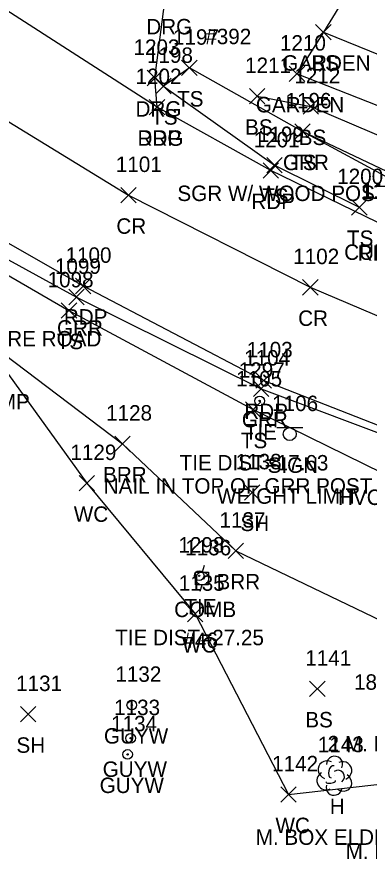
# Model space of a CAD drawing. Extents: x 1761340 to 1763889, y 696770 to 706023.
# Drawn here: x 1761519.1 to 1761564.7, y 700804.8 to 700913.9 of the extents above; entities that cross this region are included whole.
import ezdxf

# ---------------------------------------------------------------- set-up
doc = ezdxf.new("R2010")
doc.units = 0
for name, color, linetype in [('C_A', 7, 'Continuous'), ('C_C', 7, 'Continuous'), ('C_I', 7, 'Continuous'), ('CBP', 7, 'Continuous'), ('D_C', 7, 'Continuous'), ('L_A', 7, 'Continuous'), ('L_C', 7, 'Continuous'), ('L_I', 7, 'Continuous'), ('L_TIC', 7, 'Continuous'), ('LABL', 7, 'Continuous'), ('LAPB', 7, 'Continuous'), ('LAWE', 7, 'Continuous'), ('LELB', 7, 'Continuous'), ('LTD', 7, 'Continuous'), ('P_A', 7, 'Continuous'), ('P_I', 7, 'Continuous'), ('P_TIC', 7, 'Continuous'), ('PET', 7, 'Continuous'), ('PRC', 7, 'Continuous'), ('R_A', 7, 'Continuous'), ('R_C', 7, 'Continuous'), ('R_I', 7, 'Continuous'), ('R_TIC', 7, 'Continuous'), ('RDG', 7, 'Continuous'), ('RGR', 7, 'Continuous'), ('S_A', 7, 'Continuous'), ('S_C', 7, 'Continuous'), ('S_I', 7, 'Continuous'), ('SSGN', 7, 'Continuous'), ('U_A', 7, 'Continuous'), ('U_C', 7, 'Continuous'), ('U_I', 7, 'Continuous'), ('UP', 7, 'Continuous'), ('UPGW', 7, 'Continuous')]:
    doc.layers.add(name, color=color, linetype=linetype)

msp = doc.modelspace()

# ---------------------------------------------------------------- linework, layer by layer
at = {"layer": 'CBP'}
for centre, radius in [((1761550.48, 700864.17), 0.625), ((1761550.48, 700864.17), 0.0833), ((1761542.66, 700841.54), 0.625), ((1761542.66, 700841.54), 0.0833)]:
    msp.add_circle(centre, radius, dxfattribs=at)
at = {"layer": 'L_TIC'}
for points in [[(1761557.73, 700910.94), (1761559.73, 700912.94)], [(1761559.73, 700910.94), (1761557.73, 700912.94)], [(1761557.73, 700910.94), (1761559.73, 700912.94)], [(1761559.73, 700910.94), (1761557.73, 700912.94)], [(1761557.73, 700910.94), (1761559.73, 700912.94)], [(1761559.73, 700910.94), (1761557.73, 700912.94)], [(1761540.39, 700906.3), (1761542.39, 700908.3)], [(1761542.39, 700906.3), (1761540.39, 700908.3)], [(1761554.32, 700905.54), (1761556.32, 700907.54)], [(1761556.32, 700905.54), (1761554.32, 700907.54)], [(1761537.03, 700903.95), (1761539.03, 700905.95)], [(1761539.03, 700903.95), (1761537.03, 700905.95)], [(1761549.16, 700902.64), (1761551.16, 700904.64)], [(1761551.16, 700902.64), (1761549.16, 700904.64)], [(1761556.1, 700901.31), (1761558.1, 700903.31)], [(1761558.1, 700901.31), (1761556.1, 700903.31)], [(1761555.02, 700898.06), (1761557.02, 700900.06)], [(1761557.02, 700898.06), (1761555.02, 700900.06)], [(1761551.4, 700893.7), (1761553.4, 700895.7)], [(1761553.4, 700893.7), (1761551.4, 700895.7)], [(1761562.38, 700888.25), (1761564.38, 700890.25)], [(1761564.38, 700888.25), (1761562.38, 700890.25)], [(1761524.81, 700874.88), (1761526.81, 700876.88)], [(1761526.81, 700874.88), (1761524.81, 700876.88)], [(1761548.64, 700862.05), (1761550.64, 700864.05)], [(1761550.64, 700862.05), (1761548.64, 700864.05)], [(1761531.73, 700857.63), (1761533.73, 700859.63)], [(1761533.73, 700857.63), (1761531.73, 700859.63)], [(1761527.13, 700852.52), (1761529.13, 700854.52)], [(1761529.13, 700852.52), (1761527.13, 700854.52)], [(1761548.51, 700851.32), (1761550.51, 700853.32)], [(1761550.51, 700851.32), (1761548.51, 700853.32)], [(1761546.41, 700843.77), (1761548.41, 700845.77)], [(1761548.41, 700843.77), (1761546.41, 700845.77)], [(1761541.13, 700835.59), (1761543.13, 700837.59)], [(1761543.13, 700835.59), (1761541.13, 700837.59)], [(1761556.95, 700825.9), (1761558.95, 700827.9)], [(1761558.95, 700825.9), (1761556.95, 700827.9)], [(1761519.52, 700822.61), (1761521.52, 700824.61)], [(1761521.52, 700822.61), (1761519.52, 700824.61)], [(1761553.23, 700812.21), (1761555.23, 700814.21)], [(1761555.23, 700812.21), (1761553.23, 700814.21)]]:
    msp.add_lwpolyline(points, dxfattribs=at)
at = {"layer": 'LABL'}
msp.add_lwpolyline([(1761502.66, 700832.33), (1761503.71, 700859.79), (1761494.96, 700875.25), (1761503.4, 700881.5), (1761510.45, 700875.51), (1761532.73, 700858.63), (1761547.41, 700844.77), (1761568.49, 700834.64), (1761575.59, 700833.99)], dxfattribs=at)
at = {"layer": 'LAPB'}
for points in [[(1761558.73, 700911.94), (1761555.32, 700906.54), (1761591.97, 700892.11), (1761594.9, 700897.25)], [(1761558.73, 700911.94), (1761594.9, 700897.25)]]:
    msp.add_lwpolyline(points, dxfattribs=at)
at = {"layer": 'LAWE'}
msp.add_lwpolyline([(1761514.71, 700872.07), (1761528.13, 700853.52), (1761542.13, 700836.59), (1761554.23, 700813.21), (1761575.51, 700815.64)], dxfattribs=at)
at = {"layer": 'LELB'}
for points in [[(1761570.3, 700930.84), (1761558.73, 700911.94)], [(1761602.62, 700879.96), (1761585.98, 700886.58), (1761568.65, 700893.05), (1761556.02, 700899.06), (1761541.39, 700907.3), (1761538.03, 700904.95), (1761552.4, 700894.7), (1761563.38, 700889.25)], [(1761550.16, 700903.64), (1761557.1, 700902.31), (1761589.88, 700888.3), (1761604.26, 700883.61)], [(1761502.66, 700832.33), (1761493.7, 700859.4), (1761488.55, 700870.2), (1761483.14, 700875.04), (1761493.67, 700887.92), (1761503.53, 700888.77), (1761525.81, 700875.88), (1761549.64, 700863.05), (1761575.92, 700850.18), (1761596.96, 700845.7)]]:
    msp.add_lwpolyline(points, dxfattribs=at)
at = {"layer": 'LTD'}
msp.add_line((1761560.13, 700815.69), (1761560.13, 700815.69), dxfattribs=at)
msp.add_line((1761560.13, 700815.69), (1761560.13, 700815.69), dxfattribs=at)
msp.add_arc((1761560.18, 700817.12), 1.05, 335.5272, 180.9563, dxfattribs=at)
for centre, major_axis, ratio, start_param, end_param in [((1761559.34, 700816.36), (1.21, -0.51), 0.895232, 1.570796, 4.712389), ((1761561.18, 700816.27), (-1.14, -0.48), 0.949671, 1.570796, 4.712389), ((1761559.93, 700816.15), (-0.208, -0.792), 0.645439, 3.141593, 6.283185), ((1761560.63, 700815.52), (-0.5, 0.667), 0.989748, 3.141593, 6.283185), ((1761559.05, 700814.98), (0.58, -1.04), 0.959034, 3.141593, 6.283185), ((1761561.13, 700814.86), (-1.09, 0.79), 0.841452, 1.570796, 4.712389), ((1761560.13, 700814.19), (0.26, 1.06), 0.942809, 1.570796, 4.712389), ((1761559.68, 700814.94), (-0.625, -0.083), 0.423636, 0, 3.141593)]:
    msp.add_ellipse(centre, major_axis=major_axis, ratio=ratio, start_param=start_param, end_param=end_param, dxfattribs=at)
at = {"layer": 'P_TIC'}
for points in [[(1761536.2, 700901.21), (1761538.2, 700903.21)], [(1761538.2, 700901.21), (1761536.2, 700903.21)], [(1761550.93, 700893.01), (1761552.93, 700895.01)], [(1761552.93, 700893.01), (1761550.93, 700895.01)], [(1761532.51, 700889.82), (1761534.51, 700891.82)], [(1761534.51, 700889.82), (1761532.51, 700891.82)], [(1761526.65, 700878.06), (1761528.65, 700880.06)], [(1761528.65, 700878.06), (1761526.65, 700880.06)], [(1761556.04, 700877.89), (1761558.04, 700879.89)], [(1761558.04, 700877.89), (1761556.04, 700879.89)], [(1761550.01, 700865.82), (1761552.01, 700867.82)], [(1761552.01, 700865.82), (1761550.01, 700867.82)]]:
    msp.add_lwpolyline(points, dxfattribs=at)
at = {"layer": 'PET'}
for points in [[(1761565.69, 700887.32), (1761551.93, 700894.01), (1761537.2, 700902.21), (1761507.2, 700921.56), (1761485.83, 700936.45), (1761463.82, 700956.86), (1761451.66, 700968.66), (1761442.59, 700979.07), (1761431.29, 700993.83), (1761424.05, 701005.24), (1761416.58, 701016.18), (1761400.04, 701039.88), (1761381.47, 701065.28)], [(1761361.55, 701051.07), (1761381.35, 701023.89), (1761395.32, 701004.39), (1761414.57, 700977.92), (1761433.71, 700954.24), (1761453.66, 700932.57), (1761475.8, 700912.49), (1761486.98, 700903.81), (1761500.92, 700894.3), (1761527.65, 700879.06), (1761551.01, 700866.82), (1761575.84, 700857.11)]]:
    msp.add_lwpolyline(points, dxfattribs=at)
at = {"layer": 'PRC'}
msp.add_lwpolyline([(1761371.66, 701058.14), (1761390.63, 701031.26), (1761404.65, 701011.45), (1761424.14, 700986), (1761443.93, 700962.2), (1761463.21, 700942.49), (1761486.68, 700921.95), (1761508.06, 700906.42), (1761533.51, 700890.82), (1761557.04, 700878.89), (1761580.26, 700869.03), (1761600.69, 700862.06)], dxfattribs=at)
at = {"layer": 'R_TIC'}
for points in [[(1761535.94, 700904.99), (1761537.94, 700906.99)], [(1761537.94, 700904.99), (1761535.94, 700906.99)], [(1761536.2, 700901.21), (1761538.2, 700903.21)], [(1761538.2, 700901.21), (1761536.2, 700903.21)], [(1761555.02, 700898.06), (1761557.02, 700900.06)], [(1761557.02, 700898.06), (1761555.02, 700900.06)], [(1761525.77, 700876.63), (1761527.77, 700878.63)], [(1761527.77, 700876.63), (1761525.77, 700878.63)], [(1761549.69, 700864.76), (1761551.69, 700866.76)], [(1761551.69, 700864.76), (1761549.69, 700866.76)]]:
    msp.add_lwpolyline(points, dxfattribs=at)
at = {"layer": 'RDG'}
msp.add_lwpolyline([(1761537.2, 700902.21), (1761536.94, 700905.99), (1761538.32, 700916.64), (1761542.9, 700924.39), (1761552.61, 700935.62)], dxfattribs=at)
at = {"layer": 'RGR'}
for points in [[(1761602.71, 700878.24), (1761585.07, 700884.74), (1761568.33, 700892.42), (1761556.02, 700899.06)], [(1761493.65, 700890.31), (1761499.5, 700890.83), (1761506.08, 700888.95), (1761526.77, 700877.63), (1761550.69, 700865.76), (1761575.7, 700856.34), (1761588.64, 700851.95), (1761598.08, 700849.06)]]:
    msp.add_lwpolyline(points, dxfattribs=at)
at = {"layer": 'SSGN'}
for p, q in [((1761552.73, 700860.72), (1761556.06, 700860.72)), ((1761554.38, 700859.88), (1761554.38, 700859.88))]:
    msp.add_line(p, q, dxfattribs=at)
msp.add_circle((1761554.38, 700859.88), 0.833, dxfattribs=at)
at = {"layer": 'UP'}
for p, q in [((1761543.29, 700842.85), (1761543.04, 700842.02)), ((1761542.2, 700840.35), (1761542.2, 700842.02)), ((1761542.2, 700842.02), (1761543.87, 700842.02)), ((1761543.87, 700842.02), (1761543.87, 700840.35)), ((1761543.04, 700841.18), (1761543.04, 700841.18)), ((1761543.87, 700840.35), (1761542.2, 700840.35)), ((1761542.79, 700839.52), (1761543.04, 700840.35))]:
    msp.add_line(p, q, dxfattribs=at)
msp.add_circle((1761543.04, 700841.18), 0.833, dxfattribs=at)
at = {"layer": 'UPGW'}
for centre, radius in [((1761533.94, 700824.8), 0.625), ((1761533.94, 700824.8), 0.0833), ((1761533.78, 700820.49), 0.625), ((1761533.78, 700820.49), 0.0833), ((1761533.39, 700818.4), 0.625), ((1761533.39, 700818.4), 0.0833)]:
    msp.add_circle(centre, radius, dxfattribs=at)

# ---------------------------------------------------------------- texts
at = {"layer": 'C_A'}
for s, p in [('TIE', (1761548.56, 700859.17)), ('HVCTRL', (1761560.63, 700850.7)), ('TIE', (1761540.74, 700836.54))]:
    msp.add_text(s, height=2, dxfattribs=at).set_placement(p)
at = {"layer": 'C_C'}
for s, p in [('TIE DIST=17.63', (1761540.13, 700855.17)), ('NAIL IN TOP OF GRR POST', (1761530.3, 700852.17)), ('TIE DIST=27.25', (1761531.79, 700832.54))]:
    msp.add_text(s, height=2, dxfattribs=at).set_placement(p)
at = {"layer": 'C_I'}
for s, p in [('1297', (1761547.78, 700867.17)), ('1298', (1761539.97, 700844.54))]:
    msp.add_text(s, height=2, dxfattribs=at).set_placement(p)
at = {"layer": 'D_C'}
for s, p in [('12 CGMP', (1761509, 700863.07)), ('18 CGMP POOR CONDITION', (1761562.7, 700826.77))]:
    msp.add_text(s, height=2, dxfattribs=at).set_placement(p)
at = {"layer": 'L_A'}
for s, p in [('GARDEN', (1761553.4, 700906.94)), ('GARDEN', (1761553.4, 700906.94)), ('BS', (1761557.17, 700906.94)), ('TS', (1761539.8, 700902.3)), ('GARDEN', (1761549.99, 700901.54)), ('TS', (1761536.44, 700899.95)), ('BS', (1761548.6, 700898.64)), ('BS', (1761555.54, 700897.31)), ('TS', (1761554.43, 700894.06)), ('TS', (1761550.81, 700889.7)), ('TS', (1761561.79, 700884.25)), ('TS', (1761524.22, 700870.88)), ('TS', (1761548.05, 700858.05)), ('BRR', (1761530.22, 700853.63)), ('WC', (1761526.43, 700848.52)), ('SH', (1761548, 700847.32)), ('BRR', (1761544.9, 700839.77)), ('WC', (1761540.44, 700831.59)), ('BS', (1761556.39, 700821.9)), ('SH', (1761519.01, 700818.61)), ('H', (1761559.57, 700810.69)), ('WC', (1761552.53, 700808.21))]:
    msp.add_text(s, height=2, dxfattribs=at).set_placement(p)
at = {"layer": 'L_C'}
for s, p in [('2 M. BOX ELDER', (1761559.28, 700818.8)), ('M. BOX ELDER', (1761549.98, 700806.69)), ('M. BOX ELDER', (1761561.62, 700804.87))]:
    msp.add_text(s, height=2, dxfattribs=at).set_placement(p)
at = {"layer": 'L_I'}
for s, p in [('1197', (1761539.27, 700910.3)), ('1210', (1761553.11, 700909.54)), ('1198', (1761535.9, 700907.95)), ('1211', (1761548.6, 700906.64)), ('1212', (1761554.97, 700905.31)), ('1196', (1761553.83, 700902.06)), ('1199', (1761550.27, 700897.7)), ('1200', (1761560.52, 700892.25)), ('1098', (1761523.04, 700878.88)), ('1105', (1761547.44, 700866.05)), ('1128', (1761530.61, 700861.63)), ('1129', (1761525.99, 700856.52)), ('1138', (1761547.38, 700855.32)), ('1137', (1761545.29, 700847.77)), ('1135', (1761540.01, 700839.59)), ('1141', (1761556.39, 700829.9)), ('1131', (1761518.96, 700826.61)), ('1143', (1761558.01, 700818.69)), ('1142', (1761552.1, 700816.21))]:
    msp.add_text(s, height=2, dxfattribs=at).set_placement(p)
at = {"layer": 'P_A'}
for s, p in [('RDP', (1761534.68, 700897.21)), ('RDP', (1761549.41, 700889.01)), ('CR', (1761531.94, 700885.82)), ('RDP', (1761563.18, 700882.32)), ('RDP', (1761525.14, 700874.06)), ('CR', (1761555.47, 700873.89)), ('RDP', (1761548.5, 700861.82))]:
    msp.add_text(s, height=2, dxfattribs=at).set_placement(p)
at = {"layer": 'P_I'}
for s, p in [('1202', (1761534.42, 700905.21)), ('1201', (1761549.72, 700897.01)), ('1101', (1761531.87, 700893.82)), ('1195', (1761563.57, 700890.32)), ('1100', (1761525.36, 700882.06)), ('1102', (1761554.83, 700881.89)), ('1103', (1761548.81, 700869.82))]:
    msp.add_text(s, height=2, dxfattribs=at).set_placement(p)
at = {"layer": 'R_A'}
for s, p in [('DRG', (1761535.81, 700911.64)), ('DRG', (1761534.42, 700900.99)), ('DRG', (1761534.68, 700897.21)), ('GRR', (1761553.5, 700894.06)), ('CURBC', (1761561.43, 700882.44)), ('GRR', (1761524.26, 700872.63)), ('GRR', (1761548.18, 700860.76))]:
    msp.add_text(s, height=2, dxfattribs=at).set_placement(p)
at = {"layer": 'R_C'}
msp.add_text('SGR W/ WOOD POSTS', height=2, dxfattribs=at).set_placement((1761539.84, 700890.06))
at = {"layer": 'R_I'}
for s, p in [('1203', (1761534.16, 700908.99)), ('1202', (1761534.42, 700905.21)), ('1196', (1761553.83, 700902.06)), ('1194', (1761563.72, 700890.44)), ('1099', (1761523.99, 700880.63)), ('1104', (1761548.48, 700868.76))]:
    msp.add_text(s, height=2, dxfattribs=at).set_placement(p)
at = {"layer": 'S_A'}
msp.add_text('SIGN', height=2, dxfattribs=at).set_placement((1761551.51, 700854.86))
at = {"layer": 'S_C'}
for s, p in [('#392', (1761543.45, 700910.37)), ('BRIDGE ICES BEFORE ROAD', (1761492.55, 700871.23)), ('WEIGHT LIMIT', (1761544.98, 700850.86))]:
    msp.add_text(s, height=2, dxfattribs=at).set_placement(p)
at = {"layer": 'S_I'}
msp.add_text('1106', height=2, dxfattribs=at).set_placement((1761552.1, 700862.86))
at = {"layer": 'U_A'}
for s, p in [('COMB', (1761539.42, 700836.18)), ('GUYW', (1761530.33, 700819.8)), ('GUYW', (1761530.17, 700815.49)), ('GUYW', (1761529.78, 700813.4))]:
    msp.add_text(s, height=2, dxfattribs=at).set_placement(p)
at = {"layer": 'U_C'}
msp.add_text('#46', height=2, dxfattribs=at).set_placement((1761540.62, 700832.18))
at = {"layer": 'U_I'}
for s, p in [('1136', (1761540.85, 700844.18)), ('1132', (1761531.81, 700827.8)), ('1133', (1761531.65, 700823.49)), ('1134', (1761531.26, 700821.4))]:
    msp.add_text(s, height=2, dxfattribs=at).set_placement(p)

doc.saveas('drawing.dxf')
